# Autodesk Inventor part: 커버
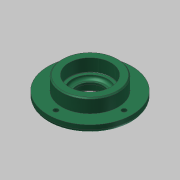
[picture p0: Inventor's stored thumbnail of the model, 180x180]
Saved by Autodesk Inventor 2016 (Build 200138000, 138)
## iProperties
Company: 한국ATC센터
Created: 2014-10
Part Number: 커버
Document SubType Name: Modeling
Designer: KYOUNG IL JANG
Density: 2.71 g/cm^3
Mass: 121.214 g
Surface Area: 161.165 cm^2
Volume: 44.7286 cm^3
Material: 알루미늄 6061
Appearance: 알루미늄 - 평지
Author: KYOUNG IL JANG
Revision Number: 1
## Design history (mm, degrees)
sketch "스케치1"
  geometry: C1 r 40 at (0, 0); 1 further point
  constraints: 1 centre point, 1 coincident
  dimensions: "d0" = 80 diameter of C1
extrude "돌출1" new body sketch "스케치1" distance "d1" = 7; taper "d2" = 0 deg
sketch "스케치2"
  geometry: C1 r 27 at (0, 0); 1 further point
  constraints: 1 centre point, 1 coincident
  dimensions: "d3" = 54 diameter of C1
extrude "돌출2" join sketch "스케치2" distance "d4" = 13; taper "d5" = 0 deg
sketch "스케치3"
  geometry: C1 r 20 at (0, 0); 1 further point
  constraints: 1 centre point, 1 coincident
  dimensions: "d6" = 40 diameter of C1
extrude "돌출3" join sketch "스케치3" distance "d7" = 5; taper "d8" = 0 deg
hole "구멍1" diameter "d11" = 25; stored, may be unused: countersink angle "d15" = 90 deg, drill point angle "d17" = 118 deg; dims "d9" = 10, "d10" = 10, "d12" = 6, "d13" = 32, "d14" = 8.3, "d16" = 8
hole "구멍2" diameter "d20" = 34; stored, may be unused: countersink angle "d24" = 90 deg, drill point angle "d26" = 0 deg; dims "d18" = 10, "d19" = 10, "d21" = 6, "d22" = 40, "d23" = 12, "d25" = 3
fillet "모깎기2" dims "d34" = 3
fillet "모깎기1" dims "d27" = 0.3
chamfer "모따기1" distance "d28" = 1; stored, may be unused: second distance "d29" = 2, angle "d30" = 45 deg
chamfer "모따기2" distance "d31" = 1.2; stored, may be unused: second distance "d32" = 2, angle "d33" = 30 deg
sketch "스케치4" dims "d35" = 65
  geometry: 3 further points
  constraints: 2 horizontal alignment, 1 coincident, 2 other
hole "구멍3" sketch "스케치4" at (32.5, 0) diameter "d36" = 4.5; stored, may be unused: countersink angle "d40" = 90 deg, drill point angle "d42" = 118 deg; dims "d37" = 6, "d38" = 8, "d39" = 4.4, "d41" = 13
node "솔리드1"
pattern_circular "원형 패턴1" dims angle "d44" = 360 deg
